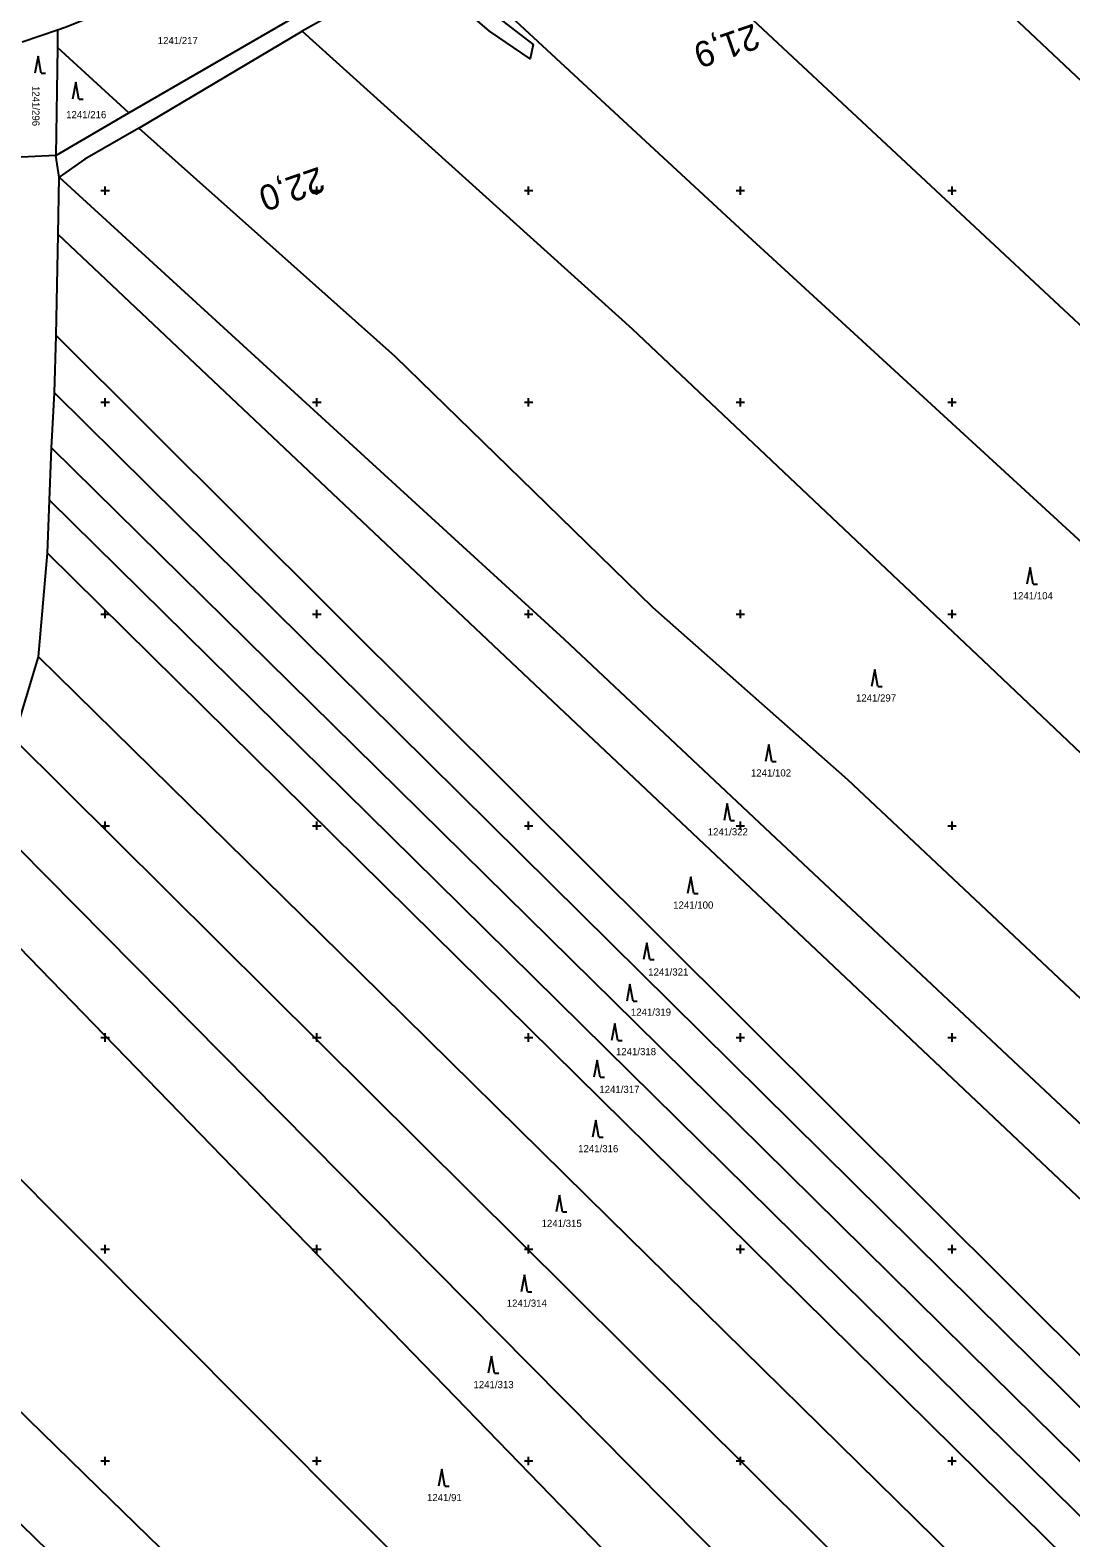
# Model space of a CAD drawing. Extents: x -776734 to -748832, y -1118122 to -976986.
# Drawn here: x -751617.7 to -751372, y -1115218.2 to -1114862.1 of the extents above; entities that cross this region are included whole.
import ezdxf

# ---------------------------------------------------------------- set-up
doc = ezdxf.new("R2010")
doc.units = 0
for name, color, linetype in [('KM_Hranice parcel', 7, 'Continuous'), ('KM_Parcelní čísla', 7, 'Continuous'), ('KM_Značky kultur', 7, 'Continuous'), ('Level 61 Křížky', 7, 'Continuous'), ('SŽG Vrstva 7', 7, 'Continuous')]:
    doc.layers.add(name, color=color, linetype=linetype)

msp = doc.modelspace()

# ---------------------------------------------------------------- linework, layer by layer
at = {"layer": 'KM_Hranice parcel'}
for p, q in [((-751594.4, -1114881.65), (-751555.98, -1114859.47)), ((-751611.28, -1114862.12), (-751619.58, -1114864.94)), ((-751611.28, -1114862.12), (-751611.22, -1114866.19)), ((-751592.08, -1114885.24), (-751553.51, -1114862.32)), ((-751611.22, -1114866.19), (-751611.61, -1114891.73)), ((-751594.4, -1114881.65), (-751611.22, -1114866.19)), ((-751611.61, -1114891.73), (-751594.4, -1114881.65)), ((-751611.61, -1114891.73), (-751619.8, -1114892.13)), ((-751610.82, -1114896.82), (-751611.61, -1114891.73)), ((-751611.09, -1114910.41), (-751610.82, -1114896.82)), ((-751611.54, -1114934.25), (-751611.09, -1114910.41)), ((-751611.99, -1114947.76), (-751611.54, -1114934.25)), ((-751612.64, -1114960.72), (-751611.99, -1114947.76)), ((-751613.13, -1114973.12), (-751612.64, -1114960.72)), ((-751613.63, -1114985.63), (-751613.13, -1114973.12)), ((-751615.7, -1115010.07), (-751613.63, -1114985.63)), ((-751621.58, -1115029.44), (-751615.7, -1115010.07))]:
    msp.add_line(p, q, dxfattribs=at)
for points in [[(-751443.69, -1114804.18), (-751399.31, -1114846.01), (-751301.43, -1114938.25), (-751247.36, -1114989.2), (-751162.62, -1115069.38)], [(-751189.28, -1115100.15), (-751276.21, -1115019.03), (-751330.45, -1114968.42), (-751434.03, -1114871.78), (-751492.77, -1114816.96)], [(-751569.13, -1114845.24), (-751609.21, -1114861.38), (-751611.28, -1114862.12)], [(-751517.79, -1114846.24), (-751513.32, -1114854.49), (-751507.1, -1114859.18), (-751498.89, -1114865.53), (-751499.66, -1114868.86), (-751509.24, -1114862.39), (-751516.07, -1114856.48), (-751524.6, -1114849.16), (-751529.26, -1114848.74), (-751553.51, -1114862.32)], [(-751216.94, -1115124.17), (-751273.44, -1115071.63), (-751359.58, -1114992.07), (-751449.07, -1114909.92), (-751517.79, -1114846.24)], [(-751553.51, -1114862.32), (-751475.54, -1114932.68), (-751391.24, -1115012.33), (-751316.82, -1115082.92), (-751244.92, -1115151.14)], [(-751592.08, -1114885.24), (-751604.82, -1114892.62), (-751610.82, -1114896.82)], [(-751276.03, -1115181.12), (-751348.6, -1115110.66), (-751424.62, -1115039.17), (-751470.64, -1114998.48), (-751498.76, -1114971.09), (-751531.53, -1114939.21), (-751592.08, -1114885.24)], [(-751610.82, -1114896.82), (-751491.63, -1115005.97), (-751441.62, -1115052.92), (-751364.11, -1115125.69), (-751286.63, -1115198.43)], [(-751292.41, -1115211.12), (-751373.31, -1115134.79), (-751451.65, -1115060.86), (-751495.59, -1115019.4), (-751611.09, -1114910.41)], [(-751611.54, -1114934.25), (-751502.55, -1115042.84), (-751469.94, -1115075.32), (-751384.97, -1115159.96), (-751310.44, -1115234.21)], [(-751315.64, -1115240.86), (-751387.64, -1115169.64), (-751473.51, -1115084.72), (-751508.95, -1115049.67), (-751611.99, -1114947.76)], [(-751321.27, -1115247.86), (-751390.42, -1115179.72), (-751474.79, -1115096.57), (-751515.39, -1115056.55), (-751612.64, -1114960.72)], [(-751327.12, -1115255.1), (-751392.5, -1115190.64), (-751476.05, -1115108.27), (-751521.69, -1115063.28), (-751613.13, -1114973.12)], [(-751333.03, -1115262.42), (-751393.33, -1115202.94), (-751477.33, -1115120.08), (-751528.04, -1115070.06), (-751613.63, -1114985.63)], [(-751344.61, -1115276.77), (-751394.97, -1115227.23), (-751480.94, -1115142.65), (-751539.94, -1115084.61), (-751615.7, -1115010.07)], [(-751356.99, -1115292.44), (-751403.05, -1115246.66), (-751490.29, -1115159.94), (-751549.32, -1115101.27), (-751621.58, -1115029.44)], [(-751368.11, -1115310.4), (-751418.59, -1115259.37), (-751499.72, -1115177.37), (-751558.64, -1115117.82), (-751627.48, -1115048.25)], [(-751378.65, -1115327.98), (-751433.41, -1115271.49), (-751504.7, -1115197.94), (-751567.36, -1115133.3), (-751632.94, -1115065.66)], [(-751396.88, -1115357.36), (-751455.66, -1115298.4), (-751517.85, -1115236.02), (-751585.93, -1115167.72), (-751646.49, -1115106.97)], [(-751661.35, -1115148.11), (-751601.74, -1115206.16), (-751534.09, -1115272.02), (-751481.49, -1115323.24), (-751413.91, -1115389.05)], [(-751669.82, -1115166.34), (-751607.26, -1115227.27), (-751542.69, -1115290.14), (-751499.9, -1115331.82), (-751421.37, -1115408.28)]]:
    msp.add_lwpolyline(points, dxfattribs=at)
at = {"layer": 'KM_Značky kultur'}
for p, q in [((-751615.83, -1114868.29), (-751616.58, -1114872.29)), ((-751615.08, -1114872.29), (-751615.83, -1114868.29)), ((-751615.08, -1114872.29), (-751614.084, -1114872.29)), ((-751606.93, -1114874.39), (-751607.68, -1114878.39)), ((-751606.18, -1114878.39), (-751606.93, -1114874.39)), ((-751606.18, -1114878.39), (-751605.184, -1114878.39)), ((-751381.57, -1114988.98), (-751382.32, -1114992.98)), ((-751380.82, -1114992.98), (-751381.57, -1114988.98)), ((-751380.82, -1114992.98), (-751379.824, -1114992.98)), ((-751418.27, -1115013.12), (-751419.02, -1115017.12)), ((-751417.52, -1115017.12), (-751418.27, -1115013.12)), ((-751417.52, -1115017.12), (-751416.524, -1115017.12)), ((-751443.31, -1115030.82), (-751444.06, -1115034.82)), ((-751442.56, -1115034.82), (-751443.31, -1115030.82)), ((-751442.56, -1115034.82), (-751441.564, -1115034.82)), ((-751453.09, -1115044.73), (-751453.84, -1115048.73)), ((-751452.34, -1115048.73), (-751453.09, -1115044.73)), ((-751452.34, -1115048.73), (-751451.344, -1115048.73)), ((-751461.72, -1115062.03), (-751462.47, -1115066.03)), ((-751460.97, -1115066.03), (-751461.72, -1115062.03)), ((-751460.97, -1115066.03), (-751459.974, -1115066.03)), ((-751472.09, -1115077.62), (-751472.84, -1115081.62)), ((-751471.34, -1115081.62), (-751472.09, -1115077.62)), ((-751471.34, -1115081.62), (-751470.344, -1115081.62)), ((-751476.08, -1115087.44), (-751476.83, -1115091.44)), ((-751475.33, -1115091.44), (-751476.08, -1115087.44)), ((-751475.33, -1115091.44), (-751474.334, -1115091.44)), ((-751479.67, -1115096.68), (-751480.42, -1115100.68)), ((-751478.92, -1115100.68), (-751479.67, -1115096.68)), ((-751478.92, -1115100.68), (-751477.924, -1115100.68)), ((-751483.82, -1115105.35), (-751484.57, -1115109.35)), ((-751483.07, -1115109.35), (-751483.82, -1115105.35)), ((-751483.07, -1115109.35), (-751482.074, -1115109.35)), ((-751484.13, -1115119.55), (-751484.88, -1115123.55)), ((-751483.38, -1115123.55), (-751484.13, -1115119.55)), ((-751483.38, -1115123.55), (-751482.384, -1115123.55)), ((-751492.72, -1115137.21), (-751493.47, -1115141.21)), ((-751491.97, -1115141.21), (-751492.72, -1115137.21)), ((-751491.97, -1115141.21), (-751490.974, -1115141.21)), ((-751501, -1115156.04), (-751501.75, -1115160.04)), ((-751500.25, -1115160.04), (-751501, -1115156.04)), ((-751500.25, -1115160.04), (-751499.254, -1115160.04)), ((-751508.77, -1115175.27), (-751509.52, -1115179.27)), ((-751508.02, -1115179.27), (-751508.77, -1115175.27)), ((-751508.02, -1115179.27), (-751507.024, -1115179.27)), ((-751520.51, -1115201.95), (-751521.26, -1115205.95)), ((-751519.76, -1115205.95), (-751520.51, -1115201.95)), ((-751519.76, -1115205.95), (-751518.764, -1115205.95))]:
    msp.add_line(p, q, dxfattribs=at)
at = {"layer": 'Level 61 Křížky'}
for p, q in [((-751600, -1114900), (-751600, -1114899)), ((-751550, -1114900), (-751550, -1114899)), ((-751500, -1114900), (-751500, -1114899)), ((-751450, -1114900), (-751450, -1114899)), ((-751400, -1114900), (-751400, -1114899)), ((-751601, -1114900), (-751599, -1114900)), ((-751600, -1114901), (-751600, -1114900)), ((-751551, -1114900), (-751549, -1114900)), ((-751550, -1114901), (-751550, -1114900)), ((-751501, -1114900), (-751499, -1114900)), ((-751500, -1114901), (-751500, -1114900)), ((-751451, -1114900), (-751449, -1114900)), ((-751450, -1114901), (-751450, -1114900)), ((-751401, -1114900), (-751399, -1114900)), ((-751400, -1114901), (-751400, -1114900)), ((-751600, -1114950), (-751600, -1114949)), ((-751550, -1114950), (-751550, -1114949)), ((-751500, -1114950), (-751500, -1114949)), ((-751450, -1114950), (-751450, -1114949)), ((-751400, -1114950), (-751400, -1114949)), ((-751601, -1114950), (-751599, -1114950)), ((-751600, -1114951), (-751600, -1114950)), ((-751551, -1114950), (-751549, -1114950)), ((-751550, -1114951), (-751550, -1114950)), ((-751501, -1114950), (-751499, -1114950)), ((-751500, -1114951), (-751500, -1114950)), ((-751451, -1114950), (-751449, -1114950)), ((-751450, -1114951), (-751450, -1114950)), ((-751401, -1114950), (-751399, -1114950)), ((-751400, -1114951), (-751400, -1114950)), ((-751600, -1115000), (-751600, -1114999)), ((-751550, -1115000), (-751550, -1114999)), ((-751500, -1115000), (-751500, -1114999)), ((-751450, -1115000), (-751450, -1114999)), ((-751400, -1115000), (-751400, -1114999)), ((-751601, -1115000), (-751599, -1115000)), ((-751600, -1115001), (-751600, -1115000)), ((-751551, -1115000), (-751549, -1115000)), ((-751550, -1115001), (-751550, -1115000)), ((-751501, -1115000), (-751499, -1115000)), ((-751500, -1115001), (-751500, -1115000)), ((-751451, -1115000), (-751449, -1115000)), ((-751450, -1115001), (-751450, -1115000)), ((-751401, -1115000), (-751399, -1115000)), ((-751400, -1115001), (-751400, -1115000)), ((-751600, -1115050), (-751600, -1115049)), ((-751550, -1115050), (-751550, -1115049)), ((-751500, -1115050), (-751500, -1115049)), ((-751450, -1115050), (-751450, -1115049)), ((-751400, -1115050), (-751400, -1115049)), ((-751601, -1115050), (-751599, -1115050)), ((-751600, -1115051), (-751600, -1115050)), ((-751551, -1115050), (-751549, -1115050)), ((-751550, -1115051), (-751550, -1115050)), ((-751501, -1115050), (-751499, -1115050)), ((-751500, -1115051), (-751500, -1115050)), ((-751451, -1115050), (-751449, -1115050)), ((-751450, -1115051), (-751450, -1115050)), ((-751401, -1115050), (-751399, -1115050)), ((-751400, -1115051), (-751400, -1115050)), ((-751601, -1115100), (-751599, -1115100)), ((-751600, -1115100), (-751600, -1115099)), ((-751600, -1115101), (-751600, -1115100)), ((-751551, -1115100), (-751549, -1115100)), ((-751550, -1115100), (-751550, -1115099)), ((-751550, -1115101), (-751550, -1115100)), ((-751501, -1115100), (-751499, -1115100)), ((-751500, -1115100), (-751500, -1115099)), ((-751500, -1115101), (-751500, -1115100)), ((-751451, -1115100), (-751449, -1115100)), ((-751450, -1115100), (-751450, -1115099)), ((-751450, -1115101), (-751450, -1115100)), ((-751401, -1115100), (-751399, -1115100)), ((-751400, -1115100), (-751400, -1115099)), ((-751400, -1115101), (-751400, -1115100)), ((-751601, -1115150), (-751599, -1115150)), ((-751600, -1115150), (-751600, -1115149)), ((-751600, -1115151), (-751600, -1115150)), ((-751551, -1115150), (-751549, -1115150)), ((-751550, -1115150), (-751550, -1115149)), ((-751550, -1115151), (-751550, -1115150)), ((-751501, -1115150), (-751499, -1115150)), ((-751500, -1115150), (-751500, -1115149)), ((-751500, -1115151), (-751500, -1115150)), ((-751451, -1115150), (-751449, -1115150)), ((-751450, -1115150), (-751450, -1115149)), ((-751450, -1115151), (-751450, -1115150)), ((-751401, -1115150), (-751399, -1115150)), ((-751400, -1115150), (-751400, -1115149)), ((-751400, -1115151), (-751400, -1115150)), ((-751601, -1115200), (-751599, -1115200)), ((-751600, -1115200), (-751600, -1115199)), ((-751600, -1115201), (-751600, -1115200)), ((-751551, -1115200), (-751549, -1115200)), ((-751550, -1115200), (-751550, -1115199)), ((-751550, -1115201), (-751550, -1115200)), ((-751501, -1115200), (-751499, -1115200)), ((-751500, -1115200), (-751500, -1115199)), ((-751500, -1115201), (-751500, -1115200)), ((-751451, -1115200), (-751449, -1115200)), ((-751450, -1115200), (-751450, -1115199)), ((-751450, -1115201), (-751450, -1115200)), ((-751401, -1115200), (-751399, -1115200)), ((-751400, -1115200), (-751400, -1115199)), ((-751400, -1115201), (-751400, -1115200))]:
    msp.add_line(p, q, dxfattribs=at)

# ---------------------------------------------------------------- texts
at = {"layer": 'KM_Parcelní čísla'}
for s, p in [('1241/217', (-751587.58, -1114865.42)), ('1241/216', (-751609.21, -1114882.91)), ('1241/104', (-751385.69, -1114996.53)), ('1241/297', (-751422.7, -1115020.67)), ('1241/102', (-751447.5, -1115038.37)), ('1241/322', (-751457.7, -1115052.28)), ('1241/100', (-751465.86, -1115069.58)), ('1241/321', (-751471.76, -1115085.38)), ('1241/319', (-751475.85, -1115094.86)), ('1241/318', (-751479.38, -1115104.18)), ('1241/317', (-751483.3, -1115113.11)), ('1241/316', (-751488.3, -1115127.1)), ('1241/315', (-751496.93, -1115144.76)), ('1241/314', (-751505.17, -1115163.59)), ('1241/313', (-751513.02, -1115182.82)), ('1241/91', (-751524, -1115209.5))]:
    msp.add_text(s, height=1.7, dxfattribs=at).set_placement(p)
msp.add_text('1241/296', height=1.7, rotation=270, dxfattribs=at).set_placement((-751617.2, -1114875.29))
at = {"layer": 'SŽG Vrstva 7'}
for s, rotation, p in [('21,9', 199.015719, (-751446.779, -1114860.4658)), ('22,0', 199.025979, (-751549.4721, -1114894.2926))]:
    msp.add_text(s, height=6, rotation=rotation, dxfattribs=at).set_placement(p)

doc.saveas('drawing.dxf')
